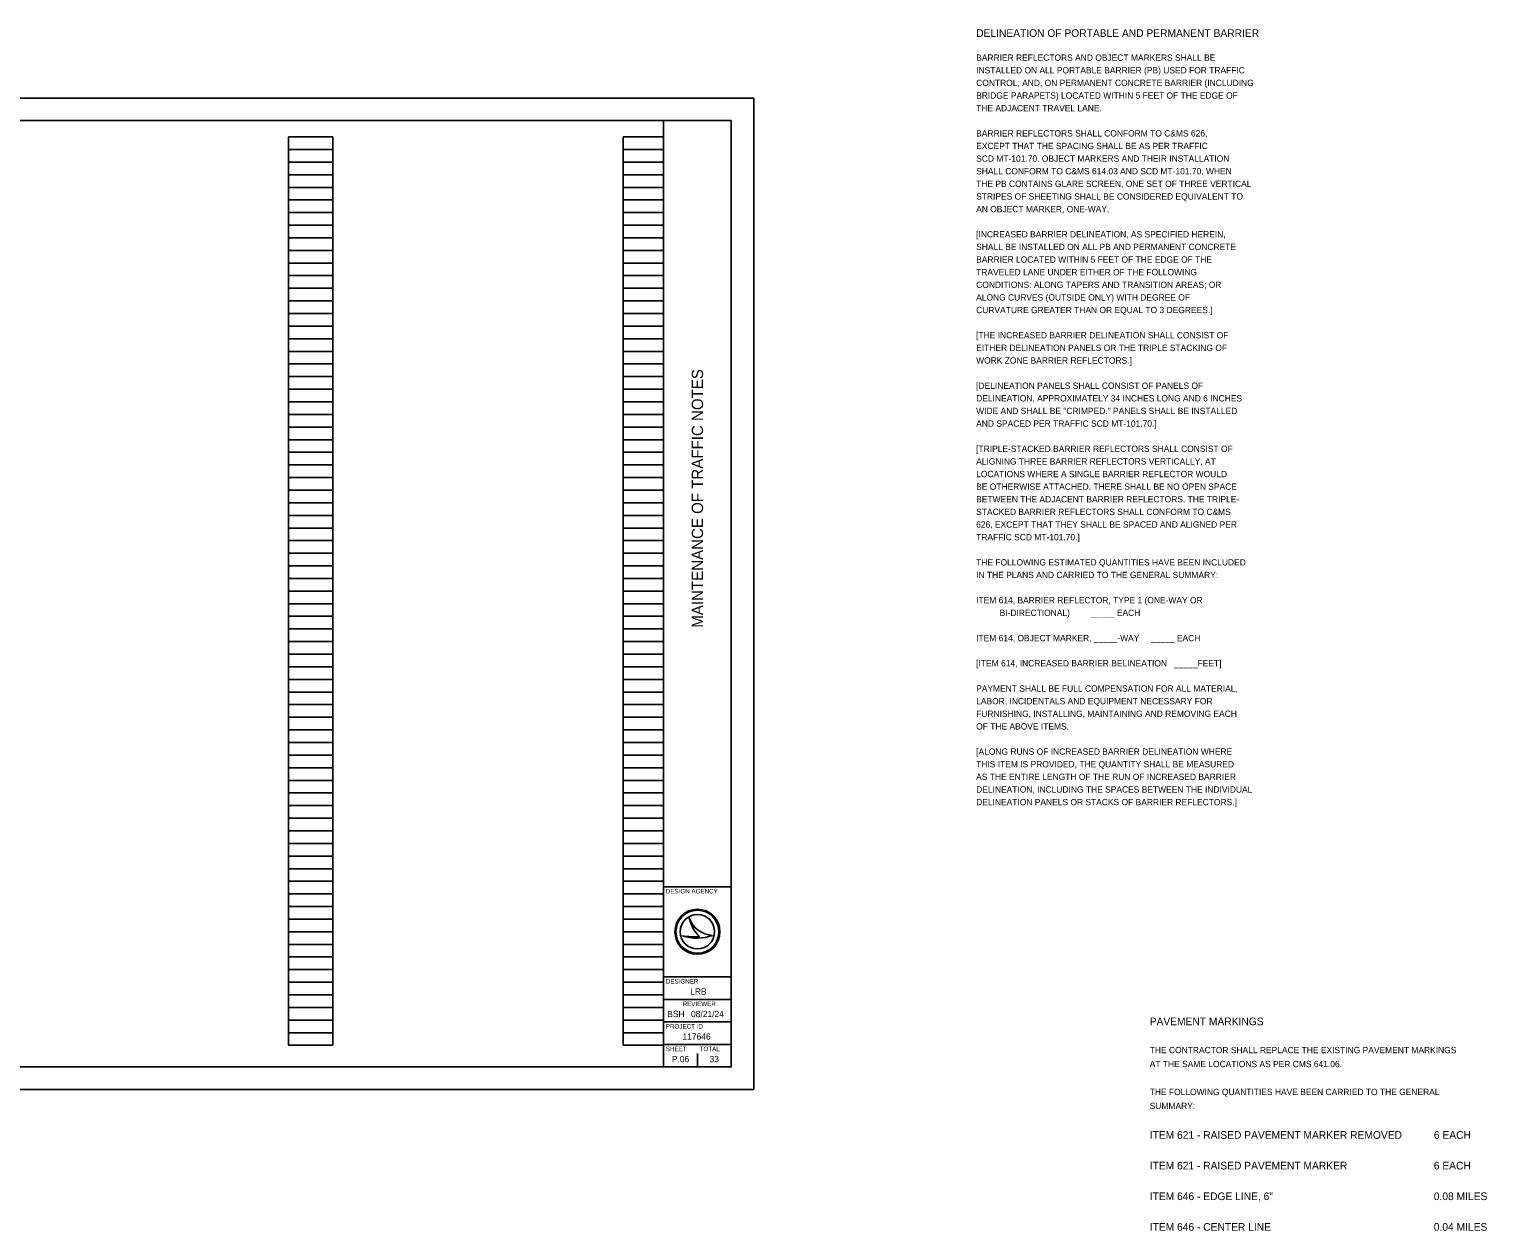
# Model space of a CAD drawing. Extents: x -18.3 to 50.3, y -3.1 to 38.9.
# Drawn here: x 17.93 to 50.26, y -3.14 to 23.53 of the extents above; entities that cross this region are included whole.
import ezdxf

# ---------------------------------------------------------------- set-up
doc = ezdxf.new("R2010")
doc.units = 0
for name, color, linetype in [('SH_Border', 7, 'Continuous'), ('SH_Cut_Line', 7, 'Continuous'), ('SH_Data', 7, 'Continuous'), ('SH_Text', 7, 'Continuous')]:
    doc.layers.add(name, color=color, linetype=linetype)

msp = doc.modelspace()

# ---------------------------------------------------------------- linework, layer by layer
at = {"layer": 'SH_Border'}
for p, q in [((32, 0.5), (32, 21.5)), ((32, 4.5), (33.5, 4.5)), ((32, 2.5), (33.5, 2.5)), ((32, 2), (33.5, 2)), ((32, 1.5), (33.5, 1.5)), ((32, 1), (33.5, 1))]:
    msp.add_line(p, q, dxfattribs=at)
msp.add_lwpolyline([(1.5, 21.5), (33.5, 21.5), (33.5, 0.5), (1.5, 0.5)], close=True, dxfattribs=at)
at = {"layer": 'SH_Cut_Line'}
msp.add_lwpolyline([(0, 0), (34, 0), (34, 22), (0, 22)], close=True, dxfattribs=at)
at = {"layer": 'SH_Data'}
for p, q in [((23.68, 0.98), (23.68, 21.14)), ((23.68, 21.14), (24.66, 21.14)), ((24.66, 0.98), (24.66, 21.14)), ((31.1, 0.98), (31.1, 21.14)), ((31.1, 21.14), (32, 21.14)), ((32, 0.98), (32, 21.14)), ((23.68, 20.86), (24.66, 20.86)), ((31.1, 20.86), (32, 20.86)), ((23.68, 20.58), (24.66, 20.58)), ((31.1, 20.58), (32, 20.58)), ((23.68, 20.3), (24.66, 20.3)), ((31.1, 20.3), (32, 20.3)), ((23.68, 20.02), (24.66, 20.02)), ((23.68, 19.74), (24.66, 19.74)), ((31.1, 20.02), (32, 20.02)), ((31.1, 19.74), (32, 19.74)), ((23.68, 19.46), (24.66, 19.46)), ((31.1, 19.46), (32, 19.46)), ((23.68, 19.18), (24.66, 19.18)), ((31.1, 19.18), (32, 19.18)), ((23.68, 18.9), (24.66, 18.9)), ((31.1, 18.9), (32, 18.9)), ((23.68, 18.62), (24.66, 18.62)), ((31.1, 18.62), (32, 18.62)), ((23.68, 18.34), (24.66, 18.34)), ((31.1, 18.34), (32, 18.34)), ((23.68, 18.06), (24.66, 18.06)), ((31.1, 18.06), (32, 18.06)), ((23.68, 17.78), (24.66, 17.78)), ((23.68, 17.5), (24.66, 17.5)), ((31.1, 17.78), (32, 17.78)), ((31.1, 17.5), (32, 17.5)), ((23.68, 17.22), (24.66, 17.22)), ((31.1, 17.22), (32, 17.22)), ((23.68, 16.94), (24.66, 16.94)), ((31.1, 16.94), (32, 16.94)), ((23.68, 16.66), (24.66, 16.66)), ((31.1, 16.66), (32, 16.66)), ((23.68, 16.38), (24.66, 16.38)), ((31.1, 16.38), (32, 16.38)), ((23.68, 16.1), (24.66, 16.1)), ((31.1, 16.1), (32, 16.1)), ((23.68, 15.82), (24.66, 15.82)), ((23.68, 15.54), (24.66, 15.54)), ((31.1, 15.82), (32, 15.82)), ((31.1, 15.54), (32, 15.54)), ((23.68, 15.26), (24.66, 15.26)), ((31.1, 15.26), (32, 15.26)), ((23.68, 14.98), (24.66, 14.98)), ((31.1, 14.98), (32, 14.98)), ((23.68, 14.7), (24.66, 14.7)), ((31.1, 14.7), (32, 14.7)), ((23.68, 14.42), (24.66, 14.42)), ((31.1, 14.42), (32, 14.42)), ((23.68, 14.14), (24.66, 14.14)), ((31.1, 14.14), (32, 14.14)), ((23.68, 13.86), (24.66, 13.86)), ((31.1, 13.86), (32, 13.86)), ((23.68, 13.58), (24.66, 13.58)), ((23.68, 13.3), (24.66, 13.3)), ((31.1, 13.58), (32, 13.58)), ((31.1, 13.3), (32, 13.3)), ((23.68, 13.02), (24.66, 13.02)), ((31.1, 13.02), (32, 13.02)), ((23.68, 12.74), (24.66, 12.74)), ((31.1, 12.74), (32, 12.74)), ((23.68, 12.46), (24.66, 12.46)), ((31.1, 12.46), (32, 12.46)), ((23.68, 12.18), (24.66, 12.18)), ((31.1, 12.18), (32, 12.18)), ((23.68, 11.9), (24.66, 11.9)), ((31.1, 11.9), (32, 11.9)), ((23.68, 11.62), (24.66, 11.62)), ((23.68, 11.34), (24.66, 11.34)), ((31.1, 11.62), (32, 11.62)), ((31.1, 11.34), (32, 11.34)), ((23.68, 11.06), (24.66, 11.06)), ((31.1, 11.06), (32, 11.06)), ((23.68, 10.78), (24.66, 10.78)), ((31.1, 10.78), (32, 10.78)), ((23.68, 10.5), (24.66, 10.5)), ((31.1, 10.5), (32, 10.5)), ((23.68, 10.22), (24.66, 10.22)), ((31.1, 10.22), (32, 10.22)), ((23.68, 9.94), (24.66, 9.94)), ((31.1, 9.94), (32, 9.94)), ((23.68, 9.66), (24.66, 9.66)), ((23.68, 9.38), (24.66, 9.38)), ((31.1, 9.66), (32, 9.66)), ((31.1, 9.38), (32, 9.38)), ((23.68, 9.1), (24.66, 9.1)), ((31.1, 9.1), (32, 9.1)), ((23.68, 8.82), (24.66, 8.82)), ((31.1, 8.82), (32, 8.82)), ((23.68, 8.54), (24.66, 8.54)), ((31.1, 8.54), (32, 8.54)), ((23.68, 8.26), (24.66, 8.26)), ((31.1, 8.26), (32, 8.26)), ((23.68, 7.98), (24.66, 7.98)), ((31.1, 7.98), (32, 7.98)), ((23.68, 7.7), (24.66, 7.7)), ((31.1, 7.7), (32, 7.7)), ((23.68, 7.42), (24.66, 7.42)), ((23.68, 7.14), (24.66, 7.14)), ((31.1, 7.42), (32, 7.42)), ((31.1, 7.14), (32, 7.14)), ((23.68, 6.86), (24.66, 6.86)), ((31.1, 6.86), (32, 6.86)), ((23.68, 6.58), (24.66, 6.58)), ((31.1, 6.58), (32, 6.58)), ((23.68, 6.3), (24.66, 6.3)), ((31.1, 6.3), (32, 6.3)), ((23.68, 6.02), (24.66, 6.02)), ((31.1, 6.02), (32, 6.02)), ((23.68, 5.74), (24.66, 5.74)), ((31.1, 5.74), (32, 5.74)), ((23.68, 5.46), (24.66, 5.46)), ((23.68, 5.18), (24.66, 5.18)), ((31.1, 5.46), (32, 5.46)), ((31.1, 5.18), (32, 5.18)), ((23.68, 4.9), (24.66, 4.9)), ((31.1, 4.9), (32, 4.9)), ((23.68, 4.62), (24.66, 4.62)), ((31.1, 4.62), (32, 4.62)), ((23.68, 4.34), (24.66, 4.34)), ((31.1, 4.34), (32, 4.34)), ((23.68, 4.06), (24.66, 4.06)), ((31.1, 4.06), (32, 4.06)), ((23.68, 3.78), (24.66, 3.78)), ((31.1, 3.78), (32, 3.78)), ((32.567, 3.81), (32.567, 3.81)), ((23.68, 3.5), (24.66, 3.5)), ((31.1, 3.5), (32, 3.5)), ((32.417, 3.41), (32.417, 3.41)), ((32.75, 3.5), (32.75, 3.5)), ((33.087, 3.419), (33.087, 3.419)), ((23.68, 3.22), (24.66, 3.22)), ((23.68, 2.94), (24.66, 2.94)), ((31.1, 3.22), (32, 3.22)), ((31.1, 2.94), (32, 2.94)), ((23.68, 2.66), (24.66, 2.66)), ((31.1, 2.66), (32, 2.66)), ((23.68, 2.38), (24.66, 2.38)), ((31.1, 2.38), (32, 2.38)), ((23.68, 2.1), (24.66, 2.1)), ((31.1, 2.1), (32, 2.1)), ((23.68, 1.82), (24.66, 1.82)), ((31.1, 1.82), (32, 1.82)), ((23.68, 1.54), (24.66, 1.54)), ((31.1, 1.54), (32, 1.54)), ((23.68, 1.26), (24.66, 1.26)), ((23.68, 0.98), (24.66, 0.98)), ((31.1, 1.26), (32, 1.26)), ((31.1, 0.98), (32, 0.98)), ((32.375, 0.675), (32.375, 0.675)), ((32.75, 0.5), (32.75, 0.8))]:
    msp.add_line(p, q, dxfattribs=at)
for radius in [0.5, 0.477, 0.477, 0.382]:
    msp.add_circle((32.75, 3.5), radius, dxfattribs=at)
for centre, radius, start, end in [((33.116, 3.998), 0.58, 198.9257, 198.9319), ((33.347, 3.97), 0.796, 191.6379, 191.6421), ((33.116, 3.998), 0.58, 198.9319, 267.1657), ((33.347, 3.97), 0.796, 191.6421, 226.0947), ((32.739, 4.37), 1.013, 251.4576, 290.0832), ((32.648, 4.654), 1.266, 259.4964, 259.4995), ((32.739, 4.37), 1.013, 251.4527, 251.4576), ((32.648, 4.654), 1.266, 259.4995, 276.6672)]:
    msp.add_arc(centre, radius, start, end, dxfattribs=at)

# ---------------------------------------------------------------- texts
msp.add_text('MAINTENANCE OF TRAFFIC NOTES', height=0.25, rotation=90, dxfattribs=at).set_placement((32.875, 10.247))
for s, height, p in [('DESIGN AGENCY', 0.1, (32.05, 4.35)), ('DESIGNER', 0.1, (32.05, 2.35)), ('REVIEWER', 0.1, (32.422, 1.85)), ('LRB', 0.14, (32.589, 2.105)), ('BSH', 0.14, (32.08, 1.605)), ('08/21/24', 0.14, (32.608, 1.605)), ('PROJECT ID', 0.1, (32.05, 1.35)), ('117646', 0.14, (32.419, 1.105)), ('SHEET', 0.1, (32.05, 0.85)), ('P.06', 0.14, (32.183, 0.605)), ('TOTAL', 0.1, (32.8, 0.85)), ('33', 0.14, (33.02, 0.605))]:
    msp.add_text(s, height=height, dxfattribs=at).set_placement(p)
at = {"layer": 'SH_Text'}
for s, height, p in [('DELINEATION OF PORTABLE AND PERMANENT BARRIER', 0.17, (38.934, 23.358)), ('BARRIER REFLECTORS AND OBJECT MARKERS SHALL BE', 0.14, (38.934, 22.828)), ('INSTALLED ON ALL PORTABLE BARRIER (PB) USED FOR TRAFFIC', 0.14, (38.934, 22.548)), ('CONTROL; AND, ON PERMANENT CONCRETE BARRIER (INCLUDING', 0.14, (38.934, 22.268)), ('BRIDGE PARAPETS) LOCATED WITHIN 5 FEET OF THE EDGE OF', 0.14, (38.934, 21.988)), ('THE ADJACENT TRAVEL LANE.', 0.14, (38.934, 21.708)), ('BARRIER REFLECTORS SHALL CONFORM TO C&MS 626,', 0.14, (38.934, 21.148)), ('SCD MT-101.70. OBJECT MARKERS AND THEIR INSTALLATION', 0.14, (38.934, 20.588)), ('EXCEPT THAT THE SPACING SHALL BE AS PER TRAFFIC', 0.14, (38.934, 20.868)), ('SHALL CONFORM TO C&MS 614.03 AND SCD MT-101.70. WHEN', 0.14, (38.934, 20.308)), ('THE PB CONTAINS GLARE SCREEN, ONE SET OF THREE VERTICAL', 0.14, (38.934, 20.028)), ('STRIPES OF SHEETING SHALL BE CONSIDERED EQUIVALENT TO', 0.14, (38.934, 19.748)), ('AN OBJECT MARKER, ONE-WAY.', 0.14, (38.934, 19.468)), ('SHALL BE INSTALLED ON ALL PB AND PERMANENT CONCRETE', 0.14, (38.934, 18.628)), ('[INCREASED BARRIER DELINEATION, AS SPECIFIED HEREIN,', 0.14, (38.934, 18.908)), ('BARRIER LOCATED WITHIN 5 FEET OF THE EDGE OF THE', 0.14, (38.934, 18.348)), ('TRAVELED LANE UNDER EITHER OF THE FOLLOWING', 0.14, (38.934, 18.068)), ('CONDITIONS: ALONG TAPERS AND TRANSITION AREAS; OR', 0.14, (38.934, 17.788)), ('ALONG CURVES (OUTSIDE ONLY) WITH DEGREE OF', 0.14, (38.934, 17.508)), ('CURVATURE GREATER THAN OR EQUAL TO 3 DEGREES.]', 0.14, (38.934, 17.228)), ('[THE INCREASED BARRIER DELINEATION SHALL CONSIST OF', 0.14, (38.934, 16.668)), ('EITHER DELINEATION PANELS OR THE TRIPLE STACKING OF', 0.14, (38.934, 16.388)), ('WORK ZONE BARRIER REFLECTORS.]', 0.14, (38.934, 16.108)), ('[DELINEATION PANELS SHALL CONSIST OF PANELS OF', 0.14, (38.934, 15.548)), ('DELINEATION, APPROXIMATELY 34 INCHES LONG AND 6 INCHES', 0.14, (38.934, 15.268)), ('WIDE AND SHALL BE "CRIMPED." PANELS SHALL BE INSTALLED', 0.14, (38.934, 14.988)), ('AND SPACED PER TRAFFIC SCD MT-101.70.]', 0.14, (38.934, 14.708)), ('[TRIPLE-STACKED BARRIER REFLECTORS SHALL CONSIST OF', 0.14, (38.934, 14.148)), ('ALIGNING THREE BARRIER REFLECTORS VERTICALLY, AT', 0.14, (38.934, 13.868)), ('LOCATIONS WHERE A SINGLE BARRIER REFLECTOR WOULD', 0.14, (38.934, 13.588)), ('BE OTHERWISE ATTACHED. THERE SHALL BE NO OPEN SPACE', 0.14, (38.934, 13.308)), ('BETWEEN THE ADJACENT BARRIER REFLECTORS. THE TRIPLE-', 0.14, (38.934, 13.028)), ('STACKED BARRIER REFLECTORS SHALL CONFORM TO C&MS', 0.14, (38.934, 12.748)), ('TRAFFIC SCD MT-101.70.]', 0.14, (38.934, 12.188)), ('626, EXCEPT THAT THEY SHALL BE SPACED AND ALIGNED PER', 0.14, (38.934, 12.468)), ('THE FOLLOWING ESTIMATED QUANTITIES HAVE BEEN INCLUDED', 0.14, (38.934, 11.628)), ('IN THE PLANS AND CARRIED TO THE GENERAL SUMMARY:', 0.14, (38.934, 11.348)), ('ITEM 614, BARRIER REFLECTOR, TYPE 1 (ONE-WAY OR', 0.14, (38.934, 10.788)), ('          BI-DIRECTIONAL)         _____ EACH', 0.14, (38.934, 10.508)), ('ITEM 614, OBJECT MARKER, _____-WAY     _____ EACH', 0.14, (38.934, 9.948)), ('[ITEM 614, INCREASED BARRIER BELINEATION   _____FEET]', 0.14, (38.934, 9.388)), ('PAYMENT SHALL BE FULL COMPENSATION FOR ALL MATERIAL,', 0.14, (38.934, 8.828)), ('LABOR, INCIDENTALS AND EQUIPMENT NECESSARY FOR', 0.14, (38.934, 8.548)), ('FURNISHING, INSTALLING, MAINTAINING AND REMOVING EACH', 0.14, (38.934, 8.268)), ('OF THE ABOVE ITEMS.', 0.14, (38.934, 7.988)), ('[ALONG RUNS OF INCREASED BARRIER DELINEATION WHERE', 0.14, (38.934, 7.428)), ('THIS ITEM IS PROVIDED, THE QUANTITY SHALL BE MEASURED', 0.14, (38.934, 7.148)), ('AS THE ENTIRE LENGTH OF THE RUN OF INCREASED BARRIER', 0.14, (38.934, 6.868)), ('DELINEATION, INCLUDING THE SPACES BETWEEN THE INDIVIDUAL', 0.14, (38.934, 6.588)), ('DELINEATION PANELS OR STACKS OF BARRIER REFLECTORS.]', 0.14, (38.934, 6.308)), ('PAVEMENT MARKINGS', 0.17, (42.784, 1.425)), ('THE CONTRACTOR SHALL REPLACE THE EXISTING PAVEMENT MARKINGS ', 0.14, (42.784, 0.805)), ('AT THE SAME LOCATIONS AS PER CMS 641.06.', 0.14, (42.784, 0.495)), ('THE FOLLOWING QUANTITIES HAVE BEEN CARRIED TO THE GENERAL ', 0.14, (42.784, -0.125)), ('SUMMARY: ', 0.14, (42.784, -0.435)), ('ITEM 621 - RAISED PAVEMENT MARKER REMOVED', 0.17, (42.784, -1.095)), (' 6 EACH', 0.17, (49.025, -1.095)), ('ITEM 621 - RAISED PAVEMENT MARKER', 0.17, (42.784, -1.775)), ('6 EACH', 0.17, (49.086, -1.775)), ('ITEM 646 - EDGE LINE, 6"', 0.17, (42.784, -2.455)), ('0.08 MILES', 0.17, (49.086, -2.455)), ('ITEM 646 - CENTER LINE', 0.17, (42.784, -3.135)), ('0.04 MILES', 0.17, (49.086, -3.135))]:
    msp.add_text(s, height=height, dxfattribs=at).set_placement(p)

doc.saveas('drawing.dxf')
